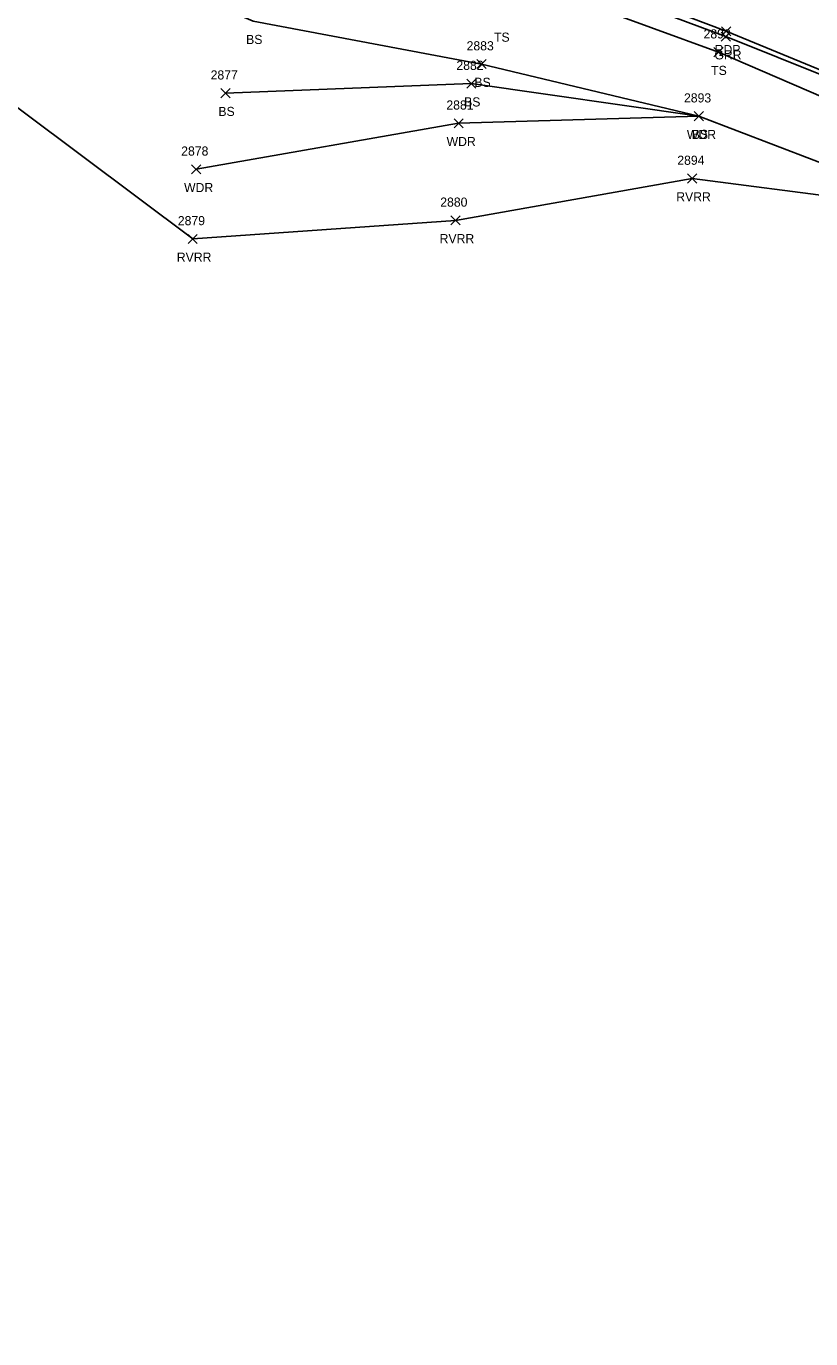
# Model space of a CAD drawing. Extents: x 1599569 to 1610055, y 642560 to 647860.
# Drawn here: x 1600349.8 to 1600521.5, y 647172.4 to 647459.9 of the extents above; entities that cross this region are included whole.
import ezdxf

# ---------------------------------------------------------------- set-up
doc = ezdxf.new("R2010")
doc.units = 0
for name, color, linetype in [('L_A', 7, 'Continuous'), ('L_I', 7, 'Continuous'), ('L_TIC', 7, 'Continuous'), ('LAWA', 7, 'Continuous'), ('LAWE', 7, 'Continuous'), ('LELB', 7, 'Continuous'), ('LSOGP', 7, 'Continuous'), ('P_A', 7, 'Continuous'), ('P_TIC', 7, 'Continuous'), ('PET', 7, 'Continuous'), ('R_A', 7, 'Continuous'), ('R_TIC', 7, 'Continuous'), ('RGR', 7, 'Continuous')]:
    doc.layers.add(name, color=color, linetype=linetype)

msp = doc.modelspace()

# ---------------------------------------------------------------- linework, layer by layer
at = {"layer": 'L_TIC'}
for points in [[(1600500.29, 647453.21), (1600502.29, 647455.21)], [(1600502.29, 647453.21), (1600500.29, 647455.21)], [(1600448.42, 647450.6), (1600450.42, 647452.6)], [(1600450.42, 647450.6), (1600448.42, 647452.6)], [(1600446.18, 647446.31), (1600448.18, 647448.31)], [(1600448.18, 647446.31), (1600446.18, 647448.31)], [(1600392.38, 647444.22), (1600394.38, 647446.22)], [(1600394.38, 647444.22), (1600392.38, 647446.22)], [(1600443.42, 647437.63), (1600445.42, 647439.63)], [(1600445.42, 647437.63), (1600443.42, 647439.63)], [(1600496.01, 647439.19), (1600498.01, 647441.19)], [(1600498.01, 647439.19), (1600496.01, 647441.19)], [(1600496.01, 647439.19), (1600498.01, 647441.19)], [(1600498.01, 647439.19), (1600496.01, 647441.19)], [(1600496.01, 647439.19), (1600498.01, 647441.19)], [(1600498.01, 647439.19), (1600496.01, 647441.19)], [(1600385.94, 647427.55), (1600387.94, 647429.55)], [(1600387.94, 647427.55), (1600385.94, 647429.55)], [(1600494.54, 647425.53), (1600496.54, 647427.53)], [(1600496.54, 647425.53), (1600494.54, 647427.53)], [(1600442.74, 647416.36), (1600444.74, 647418.36)], [(1600444.74, 647416.36), (1600442.74, 647418.36)], [(1600385.2, 647412.3), (1600387.2, 647414.3)], [(1600387.2, 647412.3), (1600385.2, 647414.3)]]:
    msp.add_lwpolyline(points, dxfattribs=at)
at = {"layer": 'LAWA'}
msp.add_lwpolyline([(1600386.94, 647428.55), (1600444.42, 647438.63), (1600497.01, 647440.19), (1600530.58, 647427.37), (1600573.26, 647409.42), (1600608.51, 647392.25), (1600655.95, 647370.95), (1600689.44, 647355.63), (1600722.44, 647339.09), (1600771.19, 647334.59)], dxfattribs=at)
at = {"layer": 'LAWE'}
msp.add_lwpolyline([(1600386.2, 647413.3), (1600443.74, 647417.36), (1600495.54, 647426.53), (1600529.31, 647422.17), (1600569.07, 647404.83), (1600609.58, 647382.71), (1600647.67, 647365.52), (1600684.38, 647351.62), (1600720.06, 647334.08), (1600758.19, 647313.61), (1600795.26, 647287.2), (1600825.21, 647273.44), (1600845.5, 647251.6), (1600858.85, 647232.88), (1600883.27, 647196.85), (1600913.08, 647172.38)], dxfattribs=at)
at = {"layer": 'LELB'}
for points in [[(1599697.61, 647759.98), (1599722.1, 647751.43), (1599744.36, 647752.34), (1599789.18, 647723.21), (1599824.42, 647706.1), (1599868.39, 647681.04), (1599912.82, 647658.19), (1599958.42, 647634.17), (1599997.43, 647618.28), (1600043.89, 647603.78), (1600086.31, 647587.76), (1600138.43, 647576.08), (1600182.57, 647557.27), (1600228.03, 647536.75), (1600266.38, 647516.33), (1600313.23, 647498.51), (1600354.12, 647480.34), (1600399.45, 647460.99), (1600449.42, 647451.6), (1600497.01, 647440.19)], [(1600055.84, 647629.73), (1600100.47, 647612.9), (1600146.77, 647594.54), (1600189.82, 647577.13), (1600237.92, 647558.86), (1600277.02, 647541.96), (1600322.78, 647524.01), (1600364.2, 647505.89), (1600375.48, 647498.79), (1600409.04, 647488.5), (1600456.88, 647470.52), (1600501.29, 647454.21), (1600533.9, 647440.09), (1600569.02, 647426.96), (1600611.34, 647410.57), (1600650.69, 647394.91), (1600690.03, 647379.36), (1600728.9, 647364.07), (1600769.48, 647348.66), (1600809.53, 647333.88)], [(1600393.38, 647445.22), (1600447.18, 647447.31), (1600497.01, 647440.19)]]:
    msp.add_lwpolyline(points, dxfattribs=at)
at = {"layer": 'LSOGP'}
msp.add_lwpolyline([(1600070.65, 647558.33), (1600121.43, 647538.97), (1600161.93, 647520.51), (1600212, 647501.45), (1600250.01, 647482.64), (1600296.6, 647464.05), (1600337.09, 647450.04), (1600386.21, 647413.3), (1600443.74, 647417.36), (1600495.54, 647426.53), (1600529.31, 647422.18), (1600569.07, 647404.83), (1600609.57, 647382.72), (1600647.67, 647365.52), (1600684.38, 647351.62), (1600720.06, 647334.08), (1600758.19, 647313.6), (1600795.26, 647287.19), (1600825.21, 647273.44)], dxfattribs=at)
at = {"layer": 'P_TIC'}
for points in [[(1600501.98, 647457.78), (1600503.98, 647459.78)], [(1600503.98, 647457.78), (1600501.98, 647459.78)]]:
    msp.add_lwpolyline(points, dxfattribs=at)
at = {"layer": 'PET'}
msp.add_lwpolyline([(1600057, 647632.55), (1600100.87, 647615.07), (1600147.9, 647596.67), (1600191.15, 647579.83), (1600239.1, 647561.25), (1600278.32, 647545.78), (1600324.18, 647528.07), (1600366.68, 647511.17), (1600410.28, 647494.24), (1600458.68, 647475.59), (1600502.98, 647458.78), (1600537.74, 647444.52), (1600578.73, 647428.32), (1600625.87, 647410.05), (1600676.47, 647390.02), (1600722.37, 647372.09), (1600742.13, 647364.34), (1600771.17, 647353.24), (1600818.96, 647335.1)], dxfattribs=at)
at = {"layer": 'R_TIC'}
for points in [[(1600501.92, 647456.62), (1600503.92, 647458.62)], [(1600503.92, 647456.62), (1600501.92, 647458.62)]]:
    msp.add_lwpolyline(points, dxfattribs=at)
at = {"layer": 'RGR'}
msp.add_lwpolyline([(1600375.92, 647501.33), (1600409.75, 647491.68), (1600457.98, 647474.45), (1600502.92, 647457.62), (1600537.28, 647443.8), (1600578.29, 647427.64), (1600625.5, 647409.22), (1600676.4, 647389.23), (1600721.9, 647371.23), (1600741.51, 647363.43), (1600770.59, 647352.25), (1600818.71, 647334.42), (1600868.72, 647316.7), (1600918.16, 647301.27), (1600965.58, 647287.14), (1601011.99, 647275.75), (1601059.57, 647265), (1601100.83, 647257.3), (1601109.97, 647255.84)], dxfattribs=at)

# ---------------------------------------------------------------- texts
at = {"layer": 'L_A'}
for s, p in [('BS', (1600397.89, 647455.99)), ('TS', (1600452.16, 647456.49)), ('TS', (1600499.7, 647449.21)), ('BS', (1600447.86, 647446.6)), ('BS', (1600391.82, 647440.22)), ('BS', (1600445.62, 647442.31)), ('WDR', (1600494.38, 647435.19)), ('BS', (1600495.45, 647435.19)), ('BS', (1600495.45, 647435.19)), ('WDR', (1600441.78, 647433.63)), ('WDR', (1600384.3, 647423.55)), ('RVRR', (1600492.05, 647421.53)), ('RVRR', (1600440.25, 647412.36)), ('RVRR', (1600382.72, 647408.3))]:
    msp.add_text(s, height=2, dxfattribs=at).set_placement(p)
at = {"layer": 'L_I'}
for s, p in [('2892', (1600498.03, 647457.21)), ('2883', (1600446.16, 647454.6)), ('2882', (1600443.92, 647450.31)), ('2877', (1600390.12, 647448.22)), ('2893', (1600493.75, 647443.19)), ('2893', (1600493.75, 647443.19)), ('2893', (1600493.75, 647443.19)), ('2881', (1600441.73, 647441.63)), ('2878', (1600383.68, 647431.55)), ('2894', (1600492.28, 647429.53)), ('2880', (1600440.39, 647420.36)), ('2879', (1600382.94, 647416.3))]:
    msp.add_text(s, height=2, dxfattribs=at).set_placement(p)
at = {"layer": 'P_A'}
msp.add_text('RDP', height=2, dxfattribs=at).set_placement((1600500.47, 647453.78))
at = {"layer": 'R_A'}
msp.add_text('GRR', height=2, dxfattribs=at).set_placement((1600500.41, 647452.62))

doc.saveas('drawing.dxf')
